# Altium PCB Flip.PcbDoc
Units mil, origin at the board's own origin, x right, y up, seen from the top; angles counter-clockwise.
Board outline 2000 x 1094.88 mil, 4 copper layers (Top Layer, Signal 1, Signal 2, Bottom Layer), stack 23.756 mil thick; 95 components, 90 nets, 410 pads, 177 vias.
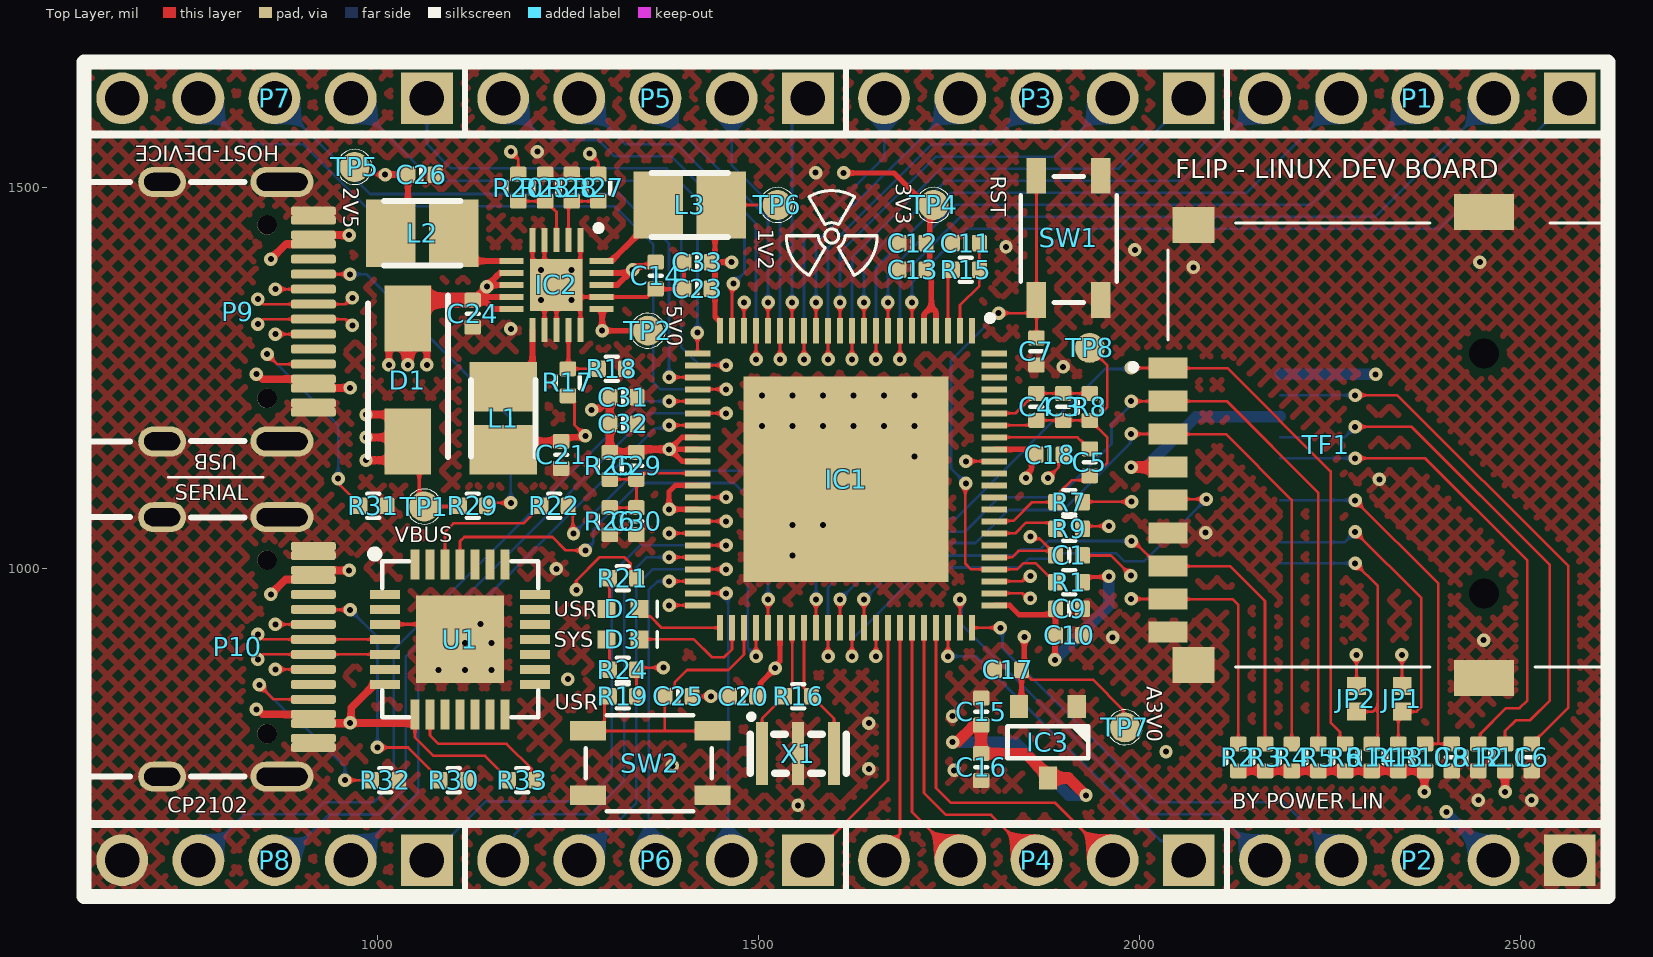
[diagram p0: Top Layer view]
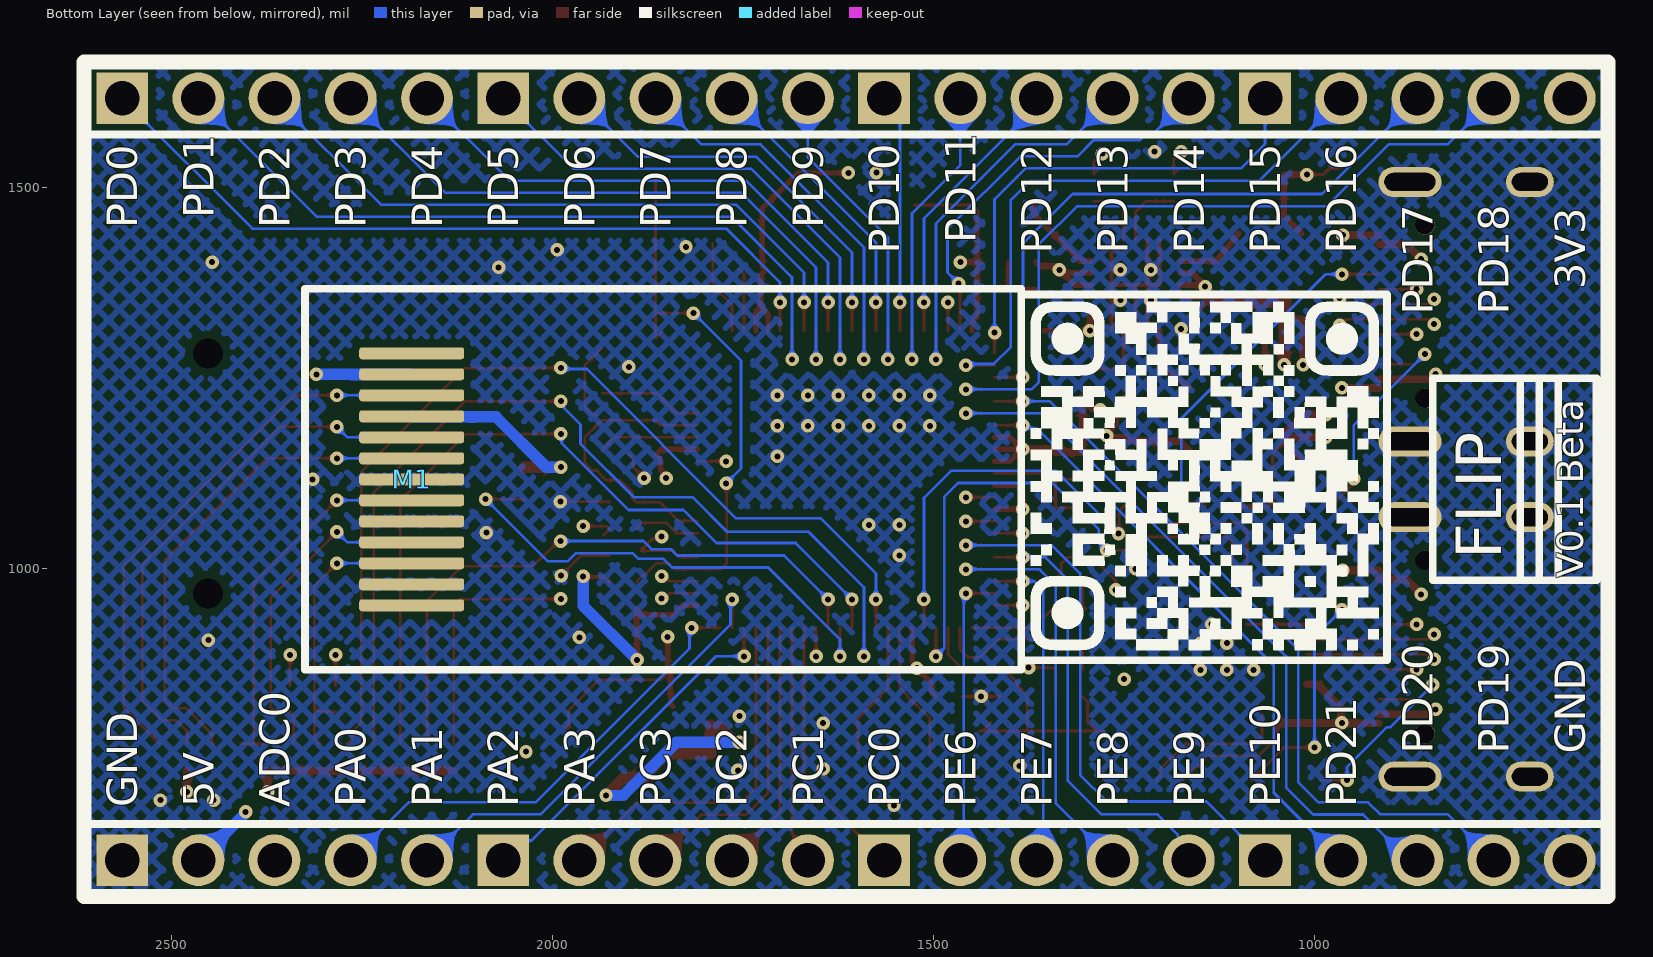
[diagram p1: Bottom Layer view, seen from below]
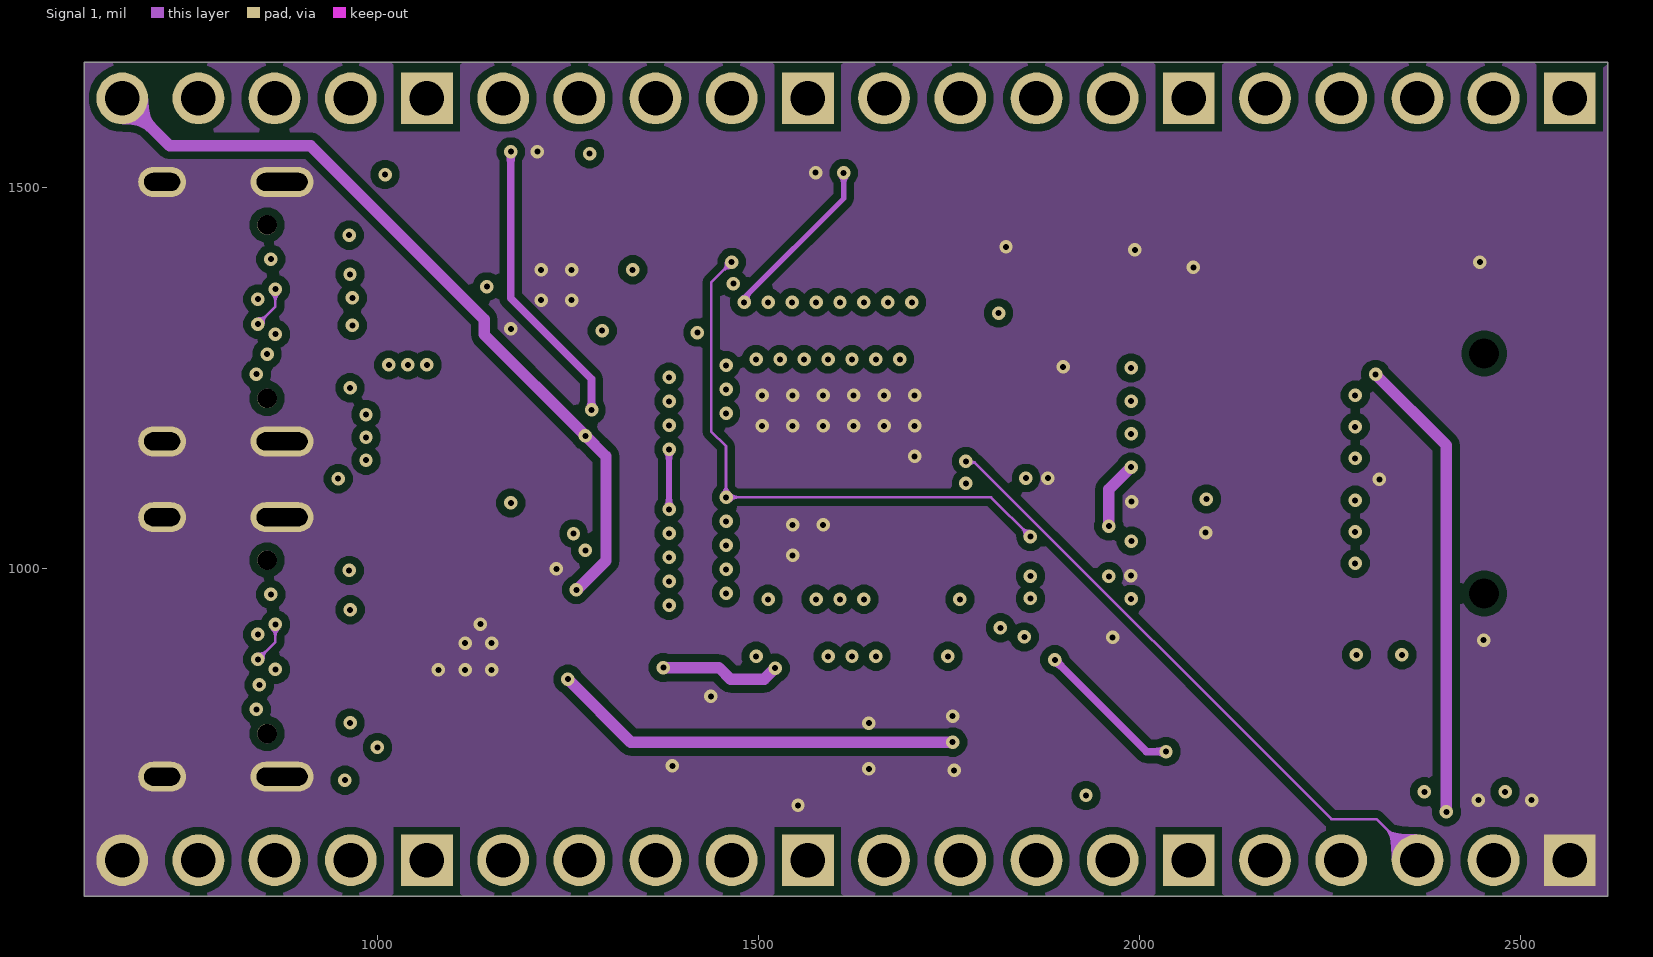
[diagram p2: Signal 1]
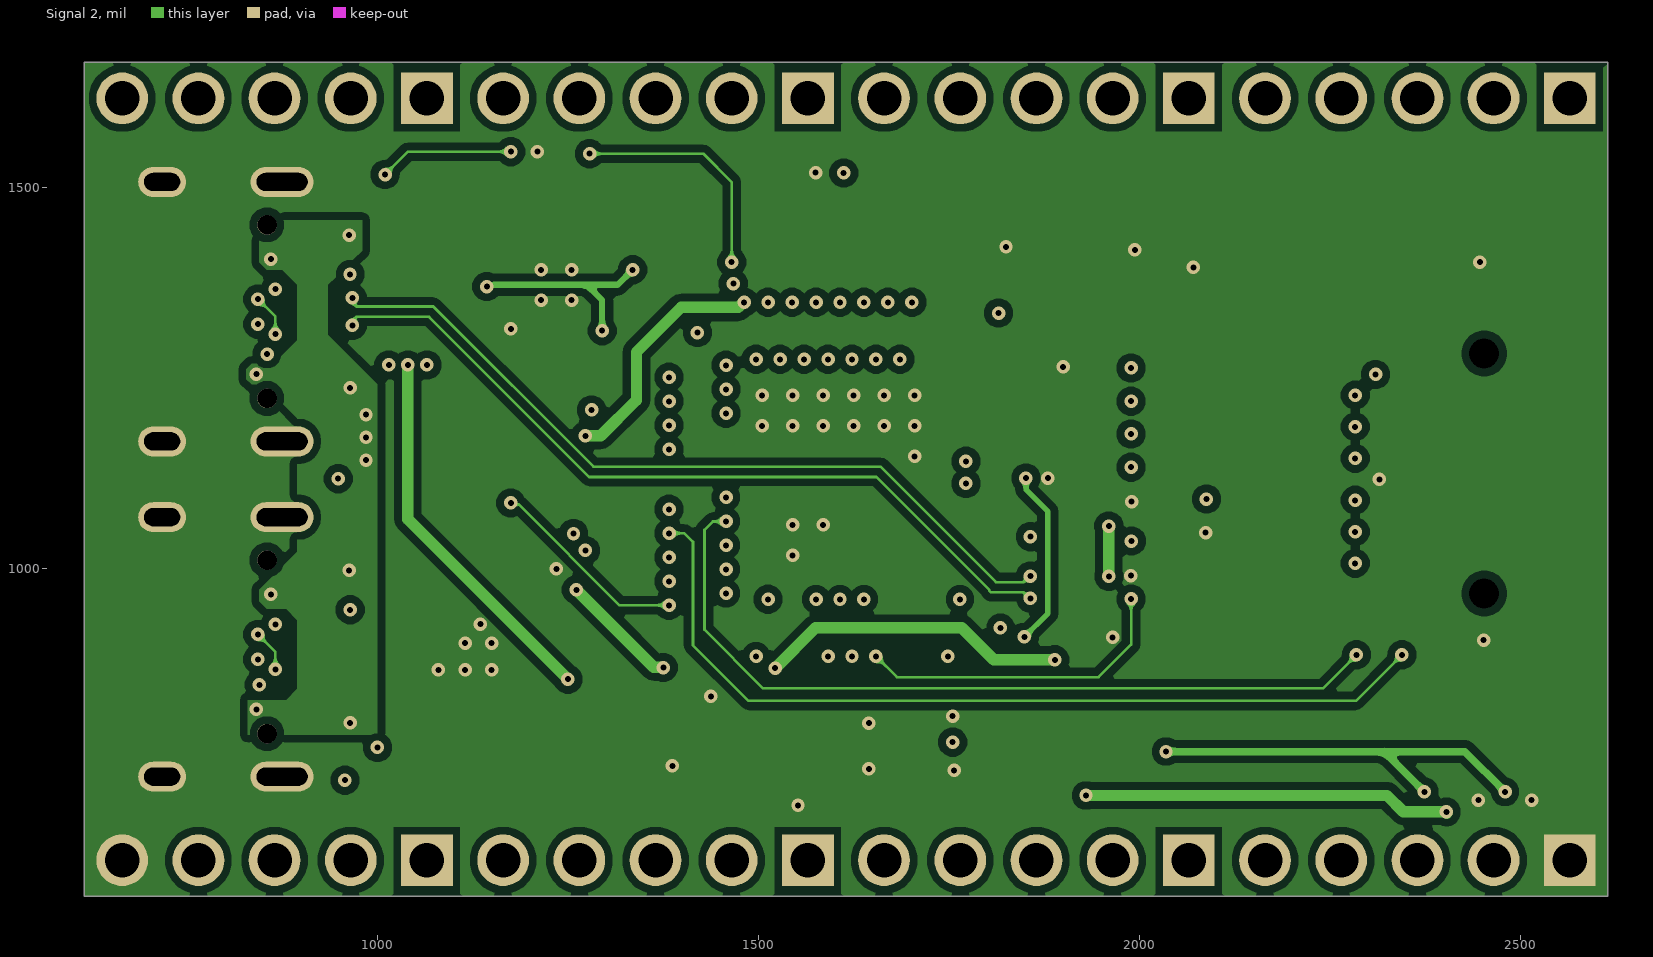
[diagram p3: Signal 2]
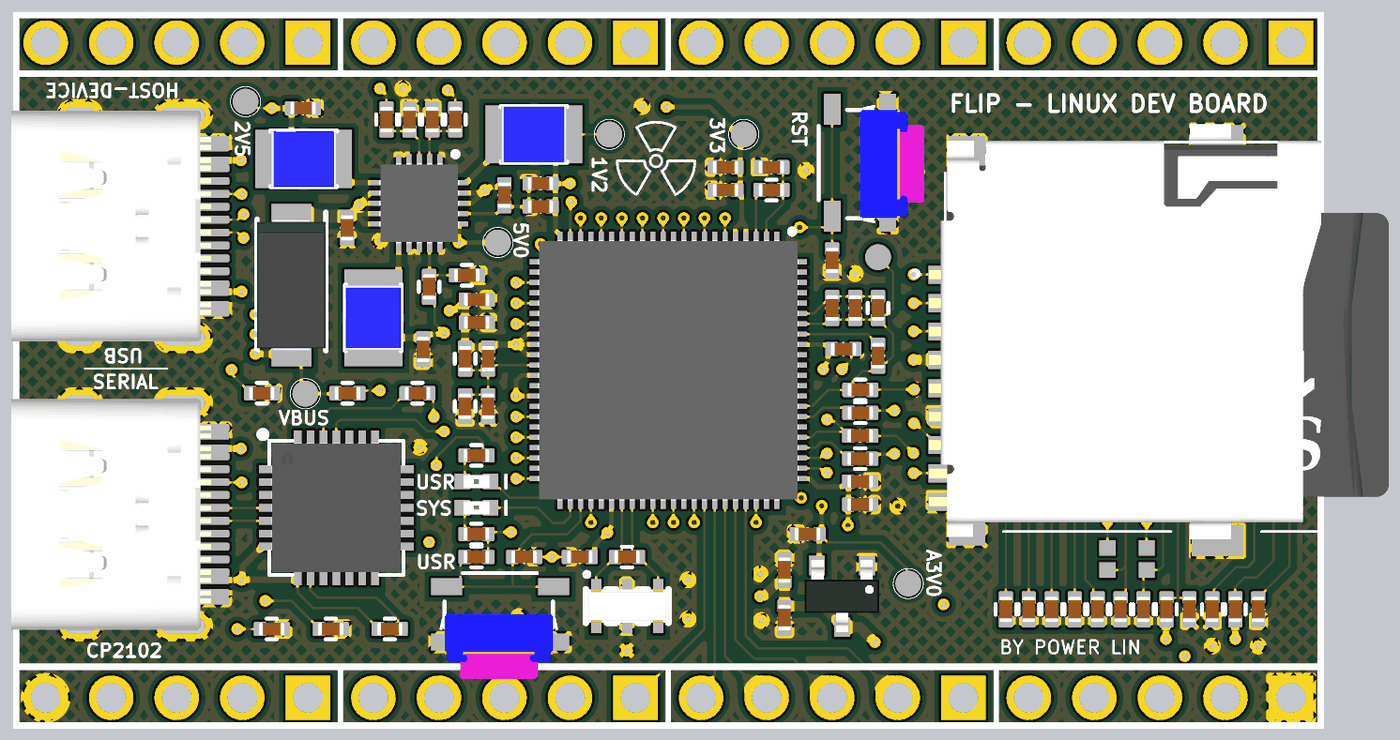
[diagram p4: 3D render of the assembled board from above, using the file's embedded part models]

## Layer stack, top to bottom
Top Solder: solder mask 0.4, Solder Resist, Dk 3.5
Top Layer: signal copper 1.4
Dielectric 2: prepreg 2.8, PP-006, Dk 4.1
Signal 1: signal copper 1.378
Dielectric 1: dielectric 12.6, FR-4, Dk 4.8
Signal 2: signal copper 1.378
Dielectric 3: prepreg 2.8, PP-006, Dk 4.1
Bottom Layer: signal copper 1.4
Bottom Solder: solder mask 0.4, Solder Resist, Dk 3.5

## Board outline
615,570 615,1664.88 2615,1664.88 2615,570

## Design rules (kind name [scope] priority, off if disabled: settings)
Clearance [All] p1: gap=0 ignorepadtopadclearanceinfootprint=TRUE except(10: Arc-Fill Arc-Poly Arc-Region Track-Fill Track-Poly Track-Region SMDPad-Fill SMDPad-Poly SMDPad-Region THPad-Fill THPad-Poly THPad-Region Via-Fill Via-Poly Via-Region Fill-Fill Fill-Poly Fill-Region Poly-Poly Poly-Region Region-Region)
DiffPairsRouting [All] p1: maxlimit=10 minlimit=10 mostfreqgap=10 toplayer_minwidth=3.5 toplayer_maxwidth=15 toplayer_prefwidth=3.5 midlayer1_minwidth=3.5 midlayer1_maxwidth=15 midlayer1_prefwidth=3.5 midlayer2_minwidth=3.5 midlayer2_maxwidth=15 midlayer2_prefwidth=3.5 bottomlayer_minwidth=3.5 bottomlayer_maxwidth=15 bottomlayer_prefwidth=3.5 maxuncoupledlength=500
PolygonConnect [All] p1: connectstyle=Direct reliefconductorwidth=10 reliefentries=4 polygonreliefangle="90 Angle" airgapwidth=10
RoutingVias [All] p1: holewidth=7.87 width=17.72 viastyle="Through Hole" minholewidth=7.87 minwidth=17.72 maxholewidth=7.87 maxwidth=17.72
SolderMaskExpansion [All] p1: expansion=4 istentingtop=FALSE
Width [All] p1: maxlimit=100 minlimit=3.5 preferedwidth=3.5
29 further rules are at their usual default settings.

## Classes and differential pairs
differential pair USB: +USB_P -USB_N
differential pair USB_CP: +USB_CP_P -USB_CP_N

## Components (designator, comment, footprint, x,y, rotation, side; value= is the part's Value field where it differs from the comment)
C1 "100nF" CAP-0402 1907.72,1017.44 r180 top
C3 "100nF" CAP-0402 1900,1212.44 r90 top
C4 "10uF" CAP-0402 1865,1212.44 r270 top
C5 "1uF" CAP-0402 1935,1139.72 r90 top
C6 "10uF" CAP-0402 2515,752.44 r270 top
C7 "100nF" CAP-0402 1865,1285.16 r90 top
C8 "10uF" CAP-0402 2410,752.44 r270 top
C9 "100nF" CAP-0402 1907.72,947.44 r0 top
C10 "10uF" CAP-0402 1907.72,912.44 r180 top
C11 "1uF" CAP-0402 1772.28,1427.44 r0 top
C12 "10uF" CAP-0402 1702.28,1427.44 r0 top
C13 "100nF" CAP-0402 1702.28,1392.44 r0 top
C14 "100nF" CAP-0402 1365,1384.72 r90 top
C15 "10uF" CAP-0402 1792.28,812.44 r270 top
C16 "1uF" CAP-0402 1792.28,739.72 r270 top
C17 "10uF" CAP-0402 1827.6,867.44 r0 top
C18 "1uF" CAP-0402 1882.21,1149.82 r0 top
C20 "10uF" CAP-0402 1480,832.44 r0 top
C21 "10uF" CAP-0402 1241,1149.44 r90 top
C23 "100nF" CAP-0402 1420,1367.44 r0 top
C24 "10uF" CAP-0402 1125,1334.72 r90 top
C25 "100nF" CAP-0402 1395,832.44 r180 top
C26 "10uF" CAP-0402 1057.72,1517.44 r180 top
C29 "100nF" CAP-0402 1340,1135.16 r270 top
C30 "100nF" CAP-0402 1340,1062.44 r270 top
C31 "10uF" CAP-0402 1322.72,1225.16 r180 top
C32 "100nF" CAP-0402 1322.72,1190.16 r180 top
C33 "10uF" CAP-0402 1420,1402.44 r0 top
D1 "SS34" DO-214AC/SMA 1040,1247.44 r270 top
D2 "RED" LED-0402 1322.28,947.44 r0 top
D3 "RED" LED-0402 1322.28,907.44 r0 top
IC1 "F1C200S" QFN88P_10X10mm 1615,1117.44 r270 top locked
IC2 "EA3036C" QFN3mmx3mm-20 1235,1372.44 r270 top
IC3 "XC6206P302MR-G" SOT-23-3 1880,772.44 r90 top
JP1 "Select" 选择焊点-0402 2345,829.44 r270 top
JP2 "Select" 选择焊点-0402 2285,829.44 r270 top
L1 "2.2uH" L-1008 1165,1197.44 r270 top
L2 "2.2uH" L-1008 1058.66,1440.16 r180 top
L3 "2.2uH" L-1008 1410,1477.44 r0 top
M1 "OLED_12880" OLED_0.78INCH_12880 2185,1117.44 r0 bottom locked
P1 "HDR1x5" HDR1X5_2.54_180_BLANK 2565,1617.44 r180 top
P2 "HDR1x5" HDR1X5_2.54_180_BLANK 2565,617.44 r180 top
P3 "HDR1x5" HDR1X5_2.54_180_BLANK 2065,1617.44 r180 top
P4 "HDR1x5" HDR1X5_2.54_180_BLANK 2065,617.44 r180 top
P5 "HDR1x5" HDR1X5_2.54_180_BLANK 1565,1617.44 r180 top
P6 "HDR1x5" HDR1X5_2.54_180_BLANK 1565,617.44 r180 top
P7 "HDR1x5" HDR1X5_2.54_180_BLANK 1065,1617.44 r180 top
P8 "HDR1x5" HDR1X5_2.54_180_BLANK 1065,617.44 r180 top
P9 "TYPE-C-31-M-12" Type-C_16+4P 816.64,1337.44 r180 top locked
P10 "TYPE-C-31-M-12" Type-C_16+4P 816.64,897.44 r180 top locked
R1 "10k" R-0402 1907.72,982.44 r0 top
R2 "10k" R-0402 2130,752.44 r270 top
R3 "10k" R-0402 2165,752.44 r270 top
R4 "10k" R-0402 2200,752.44 r270 top
R5 "10k" R-0402 2235,752.44 r270 top
R6 "10k" R-0402 2270,752.44 r270 top
R7 "0R" R-0402 1908,1087.44 r0 top
R8 "10k" R-0402 1935,1212.44 r270 top
R9 "0R" R-0402 1908,1052.44 r0 top
R10 "10k" R-0402 2375,752.44 r90 top
R11 "5.1k" R-0402 2480,752.44 r90 top
R12 "560k" R-0402 2445,752.44 r90 top
R13 "10k" R-0402 2340,752.44 r90 top
R14 "10k" R-0402 2305,752.44 r90 top
R15 "22R" R-0402 1772.28,1392.44 r0 top
R16 "1M" R-0402 1552.01,832.44 r0 top
R17 "510k" R-0402 1250,1244.72 r270 top
R18 "110k" R-0402 1307.72,1262.44 r180 top
R19 "10k" R-0402 1322.28,832.44 r0 top
R20 "316k" R-0402 1185,1500.16 r90 top
R21 "5.1k" R-0402 1322.28,987.44 r180 top
R22 "200R" R-0402 1232.28,1082.44 r180 top
R23 "100k" R-0402 1220,1500.16 r270 top
R24 "5.1k" R-0402 1322.28,867.44 r180 top
R25 "5.1k" R-0402 1305,1135.16 r270 top
R26 "5.1k" R-0402 1305,1062.44 r270 top
R27 "100k" R-0402 1290,1500.16 r90 top
R28 "100k" R-0402 1255,1500.16 r270 top
R29 "56k" R-0402 1125.43,1082.44 r0 top
R30 "5.1k" R-0402 1100,722.44 r0 top
R31 "5.1k" R-0402 994.82,1082.44 r0 top
R32 "5.1k" R-0402 1010,722.44 r0 top
R33 "10k" R-0402 1190,722.44 r180 top
SW1 "KEY" KEY-4P-4.2*3.4*2.5 1907.32,1434.13 r90 top
SW2 "KEY" KEY-4P-4.2*3.4*2.5 1358.31,744.76 r0 top
TF1 "TF-01A" TF_1 2245,1162.44 r0 top locked
TP1 "TestPoint" TestPoint 1061.26,1081.58 r0 top
TP2 "TestPoint" TestPoint 1355,1312.44 r0 top
TP4 "TestPoint" TestPoint 1730,1477.44 r0 top
TP5 "TestPoint" TestPoint 970,1527.44 r0 top
TP6 "TestPoint" TestPoint 1525,1477.44 r0 top
TP7 "TestPoint" TestPoint 1981.06,791.87 r0 top
TP8 "TestPoint" TestPoint 1935,1290 r0 top
U1 "CP2102" QFN28 1108.42,907.44 r0 top locked
X1 "24MHz" SMD3213-3P 1552.11,757.44 r0 top

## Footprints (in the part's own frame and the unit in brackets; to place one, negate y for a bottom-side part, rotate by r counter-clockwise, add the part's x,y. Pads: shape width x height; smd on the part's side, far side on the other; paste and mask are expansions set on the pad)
CAP-0402 [mm]
  rrect25% 0.5x0.55 smd: 1(-0.45,0) 2(0.45,0)
  silkscreen extent 0,-0.2 0,0.2, body extent -0.5,-0.25 0.5,0.25, height 0.6
DO-214AC/SMA [mm]
  rect 2.2x1.55 smd: 1(2.05,0) 2(-2.05,0)
  silkscreen extent -2.83,-1.33 2.55,1.33, body extent -2.55,-1.33 2.55,1.33, height 2.29
HDR1X5_2.54_180_BLANK [mm]
  rect 1.725x1.725 hole 1.15: 1(0,0)
  round 1.725 hole 1.15: 2(2.54,0) 3(5.08,0) 4(7.62,0) 5(10.16,0)
  silkscreen extent -1.27,-1.2 11.43,1.2
KEY-4P-4.2*3.4*2.5 [mm] "SKRPABE010"
  rect 1.2x0.65 smd: 1(-2.075,1.075) 1(2.075,1.075) 2(-2.075,-1.075) 2(2.075,-1.075)
  silkscreen extent -2.15,-1.6 2.05,1.6, body extent -2.35,-1.6 2.25,1.6, height 2.5
L-1008 [mm]
  rect 1.65x2.25 smd: 1(-1.05,0) 2(1.05,0)
  silkscreen extent -1.28,-1.07 1.28,1.07, body extent -1.28,-1.07 1.28,1.07, height 1.2
LED-0402 [mm]
  rect 0.6x0.6 smd: 1(-0.55,0) 2(0.55,0)
  silkscreen extent 1.14,-0.25 1.14,0.25, body extent -0.5,-0.25 0.5,0.25, height 0.5
OLED_0.78INCH_12880 [mm]
  rrect50% 3.5x0.4 smd: 1(0,-4.2) 2(0,-3.5) 3(0,-2.8) 4(0,-2.1) 5(0,-1.4) 6(0,-0.7) 7(0,0) 8(0,0.7) 9(0,1.4) 10(0,2.1) 11(0,2.8) 12(0,3.5) 13(0,4.2)
  silkscreen extent -20.32,-6.35 3.56,6.35, body extent -20.18,-6.25 7.54,6.25, height 1.55
QFN3mmx3mm-20 [mm]
  rect 0.8x0.2 smd: 1(-1.5,0.8) 2(-1.5,0.4) 3(-1.5,0) 4(-1.5,-0.4) 5(-1.5,-0.8) 11(1.5,-0.8) 12(1.5,-0.4) 13(1.5,0) 14(1.5,0.4) 15(1.5,0.8)
  rect 0.2x0.8 smd: 6(-0.8,-1.5) 7(-0.4,-1.5) 8(0,-1.5) 9(0.4,-1.5) 10(0.8,-1.5) 16(0.8,1.5) 17(0.4,1.5) 18(0,1.5) 19(-0.4,1.5) 20(-0.8,1.5)
  rect 1.75x1.75 smd: 21(0,0)
  silkscreen extent -2,1.3 -1.8,1.5, body extent -1.55,-1.55 1.55,1.55, height 0.8
QFN28 [mm]
  rect 1x0.3 smd: 1(-2.5,1.5) 2(-2.5,1) 3(-2.5,0.5) 4(-2.5,0) 5(-2.5,-0.5) 6(-2.5,-1) 7(-2.5,-1.5) 15(2.5,-1.5) 16(2.5,-1) 17(2.5,-0.5) 18(2.5,0) 19(2.5,0.5) 20(2.5,1) 21(2.5,1.5)
  rect 0.3x1 smd: 8(-1.5,-2.5) 9(-1,-2.5) 10(-0.5,-2.5) 11(0,-2.5) 12(0.5,-2.5) 13(1,-2.5) 14(1.5,-2.5) 22(1.5,2.5) 23(1,2.5) 24(0.5,2.5) 25(0,2.5) 26(-0.5,2.5) 27(-1,2.5) 28(-1.5,2.5)
  rect 2.921x2.921 smd paste-3.2: 29(0,0)
  silkscreen extent -2.97,-2.6 2.6,2.97, body extent -2.5,-2.5 2.5,2.5, height 1
QFN88P_10X10mm [mm]
  rect 0.85x0.2 smd: 1(-4.95,4.2) 2(-4.95,3.8) 3(-4.95,3.4) 4(-4.95,3) 5(-4.95,2.6) 6(-4.95,2.2) 7(-4.95,1.8) 8(-4.95,1.4) 9(-4.95,1) 10(-4.95,0.6) 11(-4.95,0.2) 12(-4.95,-0.2) 13(-4.95,-0.6) 14(-4.95,-1) 15(-4.95,-1.4) 16(-4.95,-1.8) 17(-4.95,-2.2) 18(-4.95,-2.6) 19(-4.95,-3) 20(-4.95,-3.4) 21(-4.95,-3.8) 22(-4.95,-4.2) 45(4.95,-4.2) 46(4.95,-3.8) 47(4.95,-3.4) 48(4.95,-3) 49(4.95,-2.6) 50(4.95,-2.2) 51(4.95,-1.8) 52(4.95,-1.4) 53(4.95,-1) 54(4.95,-0.6) 55(4.95,-0.2) 56(4.95,0.2) 57(4.95,0.6) 58(4.95,1) 59(4.95,1.4) 60(4.95,1.8) 61(4.95,2.2) 62(4.95,2.6) 63(4.95,3) 64(4.95,3.4) 65(4.95,3.8) 66(4.95,4.2)
  rect 0.2x0.85 smd: 23(-4.2,-4.95) 24(-3.8,-4.95) 25(-3.4,-4.95) 26(-3,-4.95) 27(-2.6,-4.95) 28(-2.2,-4.95) 29(-1.8,-4.95) 30(-1.4,-4.95) 31(-1,-4.95) 32(-0.6,-4.95) 33(-0.2,-4.95) 34(0.2,-4.95) 35(0.6,-4.95) 36(1,-4.95) 37(1.4,-4.95) 38(1.8,-4.95) 39(2.2,-4.95) 40(2.6,-4.95) 41(3,-4.95) 42(3.4,-4.95) 43(3.8,-4.95) 44(4.2,-4.95) 67(4.2,4.95) 68(3.8,4.95) 69(3.4,4.95) 70(3,4.95) 71(2.6,4.95) 72(2.2,4.95) 73(1.8,4.95) 74(1.4,4.95) 75(1,4.95) 76(0.6,4.95) 77(0.2,4.95) 78(-0.2,4.95) 79(-0.6,4.95) 80(-1,4.95) 81(-1.4,4.95) 82(-1.8,4.95) 83(-2.2,4.95) 84(-2.6,4.95) 85(-3,4.95) 86(-3.4,4.95) 87(-3.8,4.95) 88(-4.2,4.95)
  rect 6.84x6.84 smd: 89(0,0)
  silkscreen extent -5.47,4.7 -5.28,4.9, body extent -5.05,-5.05 5.05,5.05, height 0.9
R-0402 [mm]
  rrect25% 0.5x0.55 smd: 1(-0.45,0) 2(0.45,0)
  silkscreen extent -0.2,-0.4 0.2,0.4, body extent -0.5,-0.25 0.5,0.25, height 0.6
SMD3213-3P [mm]
  rect 0.4x2.1 smd: 1(-1.2,0) 2(0,0) 3(1.2,0)
  silkscreen extent -1.6,-0.65 1.6,1.27, body extent -1.6,-0.65 1.6,0.65, height 0.7
SOT-23-3 [mil]
  rect 30x24 smd: 1(47,-38) 2(47,38) 3(-47,0)
  silkscreen extent -21,-53 21,53, body extent -55,-57 55,57, height 51
TestPoint [mm]
  round 1 smd: 1(0,0)
TF_1 [mm]
  rect 1.3x0.7 smd: 1(-5.275,2.56) 2(-5.275,1.46) 3(-5.275,0.36) 4(-5.275,-0.74) 5(-5.275,-1.84) 6(-5.275,-2.94) 7(-5.275,-4.04) 8(-5.275,-5.14) 9(-5.275,-6.24)
  rect 1.4x1.2 smd: 10(-4.425,-7.34) 13(-4.425,7.34)
  rect 2x1.2 smd: 11(5.275,-7.76) 12(5.275,7.76)
  round 0.5 hole 1 unplated: 14(5.275,-4.95) 15(5.275,3.05)
  silkscreen extent -6.53,-7.4 9.23,7.4, body extent -5.9,-7.7 11.92,8.4, height 2.05
Type-C_16+4P [mm]
  round 0.65 hole 0.65: 0(-0.98,2.89) 0(-0.98,-2.89)
  oval 1.6x1 hole 0.6 slot 1.2 at 0 deg: 1(2.52,4.325) 2(2.52,-4.325)
  oval 2.1x1 hole 0.6 slot 1.7 at 0 deg: 3(-1.48,-4.325) 4(-1.48,4.325)
  rrect50% 1.5x0.3 smd: A1(-2.52,-3.35) A4(-2.52,-2.55) A5(-2.52,-1.25) A6(-2.52,-0.25) A7(-2.52,0.25) A8(-2.52,1.25) A9(-2.52,2.55) A12(-2.52,3.35) B1(-2.52,3.05) B4(-2.52,2.25) B5(-2.52,1.75) B6(-2.52,0.75) B7(-2.52,-0.75) B8(-2.52,-1.75) B9(-2.52,-2.25) B12(-2.52,-3.05)
  silkscreen extent -0.22,-4.33 5.12,4.33, body extent -2.57,-4.48 5.18,4.48, height 3.26
选择焊点-0402 [mm]
  rect 0.6x0.62 smd: 1(-0.432,0) 2(0.432,0)

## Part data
C1 C3 C4 C5 C6 C7 C8 C9 C10 C11 C12 C13 C14 C15 C16 C17 C18 C20 C21 C23 C24 C25 C26 C29 C30 C31 C32 C33: library part CAP, "贴片电容", Package=0402, SuppliersPartNumber=C52923
D1: library part DIODE, "肖特基二极管", Package=SMA(DO-214AC), SuppliersPartNumber=C22452
D2 D3: library part LED, "发光二极管", Package=0603, SuppliersPartNumber=C2290
IC1: library part F1C100S/F1C200S, "SOC", Manufacturer_Name="Allwinner Technology"
IC2: "EA3036 is a 3CH power management IC for applications powered by one Li-Ion battery or a DC 5V adapter."
IC3: library part XC6206, "LDO", Manufacturer_Name=Torex, Manufacturer_Part_Number=XC6206P122MR-G, Mouser Part Number=865-XC6206P122MR-G
JP1 JP2: "选择焊点"
L1 L2 L3: library part INDUCTOR, "SRN2512-2R2M", Package=0402, SuppliersPartNumber=C32041
M1: "OLED屏"
P1 P2 P3 P4 P5 P6 P7 P8: library part HDR1x5_2.54, "Header", Manufacturer_Name="FCI Electronics", Manufacturer_Part_Number=10129378-905001BLF, Mouser Part Number=649-1012937890501BLF
P9 P10: library part USB_Type-C_16+4P, "USB Type-C 座子"
R1 R2 R3 R4 R5 R6 R7 R8 R9 R10 R11 R12 R13 R14 R15 R16 R19 R21 R22 R24 R25 R26 R29 R30 R31 R32 R33: library part RES, "贴片电阻", Package=0805, SuppliersPartNumber=C17798
R17 R18: library part RES, "RC0402FR-07510KL", Package=0805, SuppliersPartNumber=C17798
R20: library part RES, "RC0402FR-07316KL", Package=0805, SuppliersPartNumber=C17798
R23 R27 R28: library part RES, "RC0402FR-07100KL", Package=0805, SuppliersPartNumber=C17798
SW1 SW2: "按键开关"
TF1: library part TF卡座_8脚自弹, "与TF-01A封装相似则可替换"
TP1 TP2 TP4 TP5 TP6 TP7 TP8: "测试点"
U1: "CP2102-GMR"
X1: library part XTAL, "村田无源晶振"

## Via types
v1: diameter 17.72, hole 7.87, Top Layer to Bottom Layer, 177 vias

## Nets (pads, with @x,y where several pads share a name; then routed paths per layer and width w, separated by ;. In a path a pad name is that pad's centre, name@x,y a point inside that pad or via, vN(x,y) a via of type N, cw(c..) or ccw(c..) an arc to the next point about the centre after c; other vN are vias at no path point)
ADC0: IC1.79 P2.3 | length 846.8
  Top Layer w3.5: v1(1772.48,1141.06) IC1.79
  Signal 1 w3.5: v1(1772.48,1141.06) 1774.01,1139.54 1783.91,1139.54 2252,671.44 2311,671.44 P2.3
AGND: C3.1 C4.2 C5.1 IC1.74 IC1.82 R7.1 R8.2 TP8.1 | length 485.6
  Top Layer w3.5: IC1.74 1810.42,1062.86 1834.86,1062.86 1859.44,1087.44 R7.1 1896.19,1093.35 1896.19,1101.19 1911.08,1116.08 1929.07,1116.08 C5.1 1942,1129 1947.66,1129 1958.08,1139.43 1958.08,1172.37 1935.73,1194.72 R8.2 C3.1 C4.2 1858.64,1188.37 1809.94,1188.37 IC1.82 ; TP8.1 1958.08,1266.92 1958.08,1212.14 1947.66,1201.72 R8.2@1942,1201.72
AVCC_3V0: C17.2 C18.1 IC1.80 IC3.2 TP7.1 | length 599.3
  Top Layer w3.5: C17.2@1845.31,866.84 C17.2@1853.35,858.8 ; C17.2@1853.95,858.8 1858.31,854.44 1939,854.44 1978.68,814.76 TP7.1@1978.68,794.24
  Top Layer w7: IC1.80 1809.94,1156.75 1857.56,1156.75 C18.1 1858.43,1143.75 1858.43,1130.16 1851.18,1122.91 v1(1851.18,1119.06) ; IC3.2 1845.31,822.76 1845.31,866.84 C17.2 1849,871.13 v1(1849,910.44) ; TP7.1@1978.68,794.24 TP7.1
  Signal 2 w7: v1(1849,910.44) 1880,941.44 1880,1075 1851.17,1103.83 v1(1851.18,1119.06)
GND: C1.1 C6.2 C7.1 C8.2 C9.2 C10.1 C11.1 C12.1 C13.1 C14.1 C15.1 C16.2 C17.1 C18.2 C20.1 C21.1 C23.1 C24.1 C25.1 C26.1 C30.2 C31.1 C32.1 C33.1 IC1.89 IC2.1 IC2.4 IC2.5 IC2.12 IC2.13 IC2.15 IC2.17 IC2.21 IC3.1 M1.7 M1.9 M1.12 P2.1 P8.5 P9.1 P9.2 P9.3 P9.4 P9.A1 P9.A12 P9.B1 P9.B12 P10.1 P10.2 P10.3 P10.4 P10.A1 P10.A12 P10.B1 P10.B12 R7.2 R12.1 R18.1 R23.1 R26.2 R28.1 R30.2 R31.2 R32.2 SW1.2 SW2.2 TF1.6 TF1.9 TF1.10 TF1.11 TF1.12 TF1.13 U1.3 U1.29 X1.2 | length 936
  Top Layer w3.5: C14.1 1401.85,1367.01 C23.1 ; C25.1 C20.1 ; v1(1880,1119) 1894.29,1133.29 1894.29,1144.19 C18.2 ; C1.1 1962.56,1017.44 v1(1989,991) ; R7.2 1926.28,1088 v1(1990,1088)
  Top Layer w5: U1.3 U1.29@1088.74,927.13 ; IC2.5 1203.5,1372.44 IC2.21@1219.25,1372.44 ; IC2.12 IC2.21@1219.25,1372.44 ; IC2.4 IC2.21@1219.25,1372.44 ; IC2.13 IC2.21 ; IC2.15 IC2.21@1266.5,1357.15 ; IC2.1 IC2.21@1266.5,1372.44 ; C23.1@1401.85,1367.01 C14.1 1364.02,1367.01 1353.7,1356.69 IC2.17 1266.95,1356.69 IC2.21@1266.5,1357.15 ; C23.1 C33.1 ; IC2.21@1219.25,1372.44 IC2.21 ; IC2.21 IC2.21@1266.5,1372.44 ; IC2.21@1266.5,1357.15 IC2.21@1266.5,1372.44
  other v1: 1552,689.44 2445,696.44 2515,696.44 1757,735.44 1645,737.44 1387,741.44 1645,797.44 1755,806.44 1437.5,832.44 1080,867.44 1115,867.44 1150,867.44 1115,902.44 1150,902.44 2452,906.44 1965,910 1135,927.44 1235,1000 1545,1017.44 2087,1047.44 1545,1057.44 1585,1057.44 2315,1117.44 1705,1147.44 1505,1187.44 1545,1187.44 1585,1187.44 1625,1187.44 1665,1187.44 1705,1187.44 1505,1227.44 1545,1227.44 1585,1227.44 1625,1227.44 1665,1227.44 1705,1227.44 1900,1265 1175,1315 1215,1352.44 1255,1352.44 1215,1392.44 1255,1392.44 2071,1395.44 2447,1402.44 1994,1418.44 1825,1422.44 1575,1520 1210,1547.44
KEY_USR: C25.2 IC1.47 R19.1 SW2.1 | length 442
  Top Layer w3.5: SW2.1@1276.61,787.09 SW2.1@1286.91,787.09 ; R19.1 1297.96,825.83 1297.96,798.13 SW2.1@1286.91,787.09 ; SW2.1@1425,798.13 SW2.1@1436.05,787.09 ; SW2.1@1440,787.09 SW2.1@1436.05,787.09 ; IC1.47 1481.14,887.51 1460.67,867.03 1406.59,867.03 1390.12,850.56 1390.12,846.65 1377.28,833.81 C25.2 1377.28,787.37 1377,787.09 ; SW2.1@1286.91,787.09 1377,787.09 ; 1377,787.09 SW2.1@1436.05,787.09
LED_SYS: D3.2 IC1.46 | length 163.9
  Top Layer w3.5: D3.2 1415.27,907.44 1438.79,883.92 1455.2,883.92 1465.39,894.12 IC1.46
LED_USR: D2.2 IC1.45 | length 116
  Top Layer w3.5: D2.2 1354,937.38 1358.27,937.38 1373.09,922.56 IC1.45
NetC3_2: C3.2 C4.1 IC1.83 R8.1 | length 135.7
  Top Layer w3.5: IC1.83@1809.92,1204.1 1837.25,1204.1 C4.1@1863.66,1230.51 ; C4.1@1864.02,1230.16 C4.1 C3.2 R8.1
NetC5_2: C5.2 IC1.81 | length 131.4
  Top Layer w3.5: IC1.81 1918.9,1172.56 1934.02,1157.44 C5.2
NetC6_1: C6.1 M1.3 | length 724.4
  Top Layer w3.5: v1(2283.34,1227.68) 2338.7,1227.68 2563.01,1003.37 2563.01,818.16 2523.64,778.8 2523.64,778.2 2515.6,770.16 C6.1
  Bottom Layer w3.5: M1.3 v1(2283.34,1227.68)
NetC7_2: C7.2 IC1.70 R1.1 SW1.1 | length 772.8
  Top Layer w3.5: v1@1771.53,1111.97 1771.53,1006.84 1779.03,999.33 IC1.70 1839.69,999.33 1847.8,1007.44 1863.64,1007.44 1880,991.08 1881.96,991.08 1890,983.04 R1.1@1890,982.68 ; v1(1815.28,1335.56) SW1.1@1865,1335.56 ; C7.2@1856.36,1310.91 1864.4,1302.87 C7.2 SW1.1@1865,1335.56 ; SW1.1@1865,1515.83 1865,1352.44 SW1.1@1865,1335.56
  Bottom Layer w3.5: v1(1772.48,1111.97) 1752.82,1131.63 1752.82,1273.1 v1(1815.28,1335.56)
NetC8_1: C8.1 M1.8 R10.2 | length 498.3
  Top Layer w3.5: v1(2283.34,1089.88) 2392.51,980.71 2392.51,770.16 ; R10.2 2390.21,770.16 2392.51,770.16 ; C8.1 2392.51,770.16
  Bottom Layer w3.5: M1.8 v1(2283.34,1089.88)
NetC11_2: C11.2 IC1.2 R15.2 | length 125.6
  Top Layer w3.5: IC1.2@1764.63,1312.34 1764.63,1345.88 1790,1371.26 C11.2
NetC29_2: C29.2 C30.1 IC1.33 R25.2 R26.1 | length 190.7
  Top Layer w3.5: R26.1 C30.1 C29.2 ; R25.2 C29.2 ; IC1.33 1349.24,1125.31 1341.37,1117.44 C29.2
NetD2_A: D2.1 R21.2 | length 41.6
  Top Layer w3.5: D2.1 1304.57,951.38 R21.2
NetD3_A: D3.1 R24.2 | length 41.6
  Top Layer w3.5: D3.1 1304.57,903.5 R24.2
NetIC1_3: IC1.3 R15.1 | length 82.5
  Top Layer w3.5: IC1.3 1748.9,1312.36 1748.9,1386.77 R15.1
NetIC1_51: IC1.51 R16.1 X1.1 | length 182.2
  Top Layer w3.5: X1.1 1504.87,803.4 1525.27,823.8 1526.46,823.8 1534.49,831.84 1534.49,832.44 1534.49,833.73 1544.34,843.57 IC1.51@1544.34,922.56
NetIC1_52: IC1.52 R16.2 X1.3 | length 182.8
  Top Layer w3.5: IC1.52 1559.88,843.57 1569.72,833.73 R16.2@1569.72,831.84 ; R16.2 R16.2@1569.72,831.84 ; X1.3 1599.35,803.4 1578.95,823.8 1577.76,823.8 R16.2@1569.72,831.84
NetIC1_73: IC1.73 R9.1 | length 89.5
  Top Layer w3.5: IC1.73 1837.13,1046.57 1851,1060.44 1882.28,1060.44 R9.1
NetIC2_2: IC2.2 R27.1 R28.2 | length 87.3
  Top Layer w3.5: IC2.2 1250.75,1476.6 R28.2 R27.1
NetIC2_3: IC2.3 R20.1 R23.2 | length 92.7
  Top Layer w3.5: R20.1 1220.98,1482.44 1235,1468.43 IC2.3
NetIC2_6: IC2.6 L2.1 | length 93.5
  Top Layer w8: L2.1 1128.48,1403.94 IC2.6
NetIC2_11: IC2.11 L1.1 | length 94
  Top Layer w8: L1.1 1203.5,1267.26 IC2.11
NetIC2_14: IC2.14 R17.1 R18.2 | length 91
  Top Layer w3.5: R17.1 R18.2
  Top Layer w5: R17.1@1250.75,1268.28 IC2.14
  Top Layer w8: R17.1 R17.1@1250.75,1268.28
NetIC2_20: IC2.20 L3.1 | length 112
  Top Layer w8: IC2.20 1306.97,1403.94 1340.18,1437.15 1368.66,1465.63 L3.1
NetJP1_2: JP1.2 M1.10 R13.2 | length 441.7
  Top Layer w3.5: v1(2283.34,1048.54) 2369.82,962.07 2369.82,818.34 2363.92,812.44 JP1.2 2340,807.44 R13.2
  Bottom Layer w3.5: M1.10 2269.56,1034.76 v1(2283.34,1048.54)
NetJP2_2: JP2.2 M1.11 R14.2 | length 382.2
  Top Layer w3.5: v1(2283.34,1007.2) 2313.03,977.52 2313.03,818.99 ; JP2.2 2306.48,812.44 2313.03,818.99 ; R14.2 2305.69,770.16 2313.03,777.5 2313.03,818.99
  Bottom Layer w3.5: M1.11 v1(2283.34,1007.2)
NetM1_5: M1.5 R11.2 | length 704.7
  Top Layer w3.5: v1(2283.34,1186.34) 2357.56,1186.34 2538.71,1005.19 2538.71,827.05 2512.81,801.15 2494.28,801.15 2480,786.88 R11.2
  Bottom Layer w3.5: M1.5 2269.56,1172.56 v1(2283.34,1186.34)
NetM1_6: M1.6 R12.2 | length 657.8
  Top Layer w3.5: v1(2283.34,1145) 2375.28,1145 2509.31,1010.97 2509.31,827.13 2499.21,817.03 2481.29,817.03 2447.46,783.2 2447.46,772.62 R12.2
  Bottom Layer w3.5: M1.6 v1(2283.34,1145)
NetP9_B5: P9.B5 R31.1 | length 316.1
  Top Layer w3.5: v1(855.16,1281.85) 868.46,1268.54 P9.B5 ; v1(948.54,1118.28) 951.26,1115.56 951.26,1109.27 977.1,1083.43 R31.1
  Bottom Layer w3.5: v1(855.16,1281.85) 948.54,1188.47 v1(948.54,1118.28)
NetP10_A5: P10.A5 R30.1 | length 346.9
  Top Layer w3.5: P10.A5 916.27,947.07 918.48,947.07 917.6,946.19 v1(964.2,946.19) ; v1(1000,765.44) 1040.26,765.44 1082.28,723.41 R30.1
  Bottom Layer w3.5: v1(964.2,946.19) 1000,910.39 v1(1000,765.44)
NetP10_B5: P10.B5 R32.1 | length 287.8
  Top Layer w3.5: v1(845,847.44) 863.9,828.54 P10.B5 ; v1(957.36,722.44) R32.1
  Bottom Layer w3.5: v1(845,847.44) 900.26,792.18 904.83,792.18 957.36,739.64 v1(957.36,722.44)
NetR22_2: R22.2 U1.26 | length 182.8
  Top Layer w3.5: U1.26 1088.74,1048.46 1099.81,1059.54 1191.66,1059.54 1205.49,1073.36 1206.09,1073.36 1214.57,1081.84 R22.2
NetR33_1: R33.1 U1.9 | length 196.5
  Top Layer w3.5: U1.9 1069.05,781.19 1079.95,770.3 1169.48,770.3 1202.61,737.17 1202.61,727.55 R33.1
PA0/TOUCH_X1: IC1.66 P2.4 | length 625.3
  Top Layer w3.5: IC1.66 v1(1817.76,922.56)
  Bottom Layer w3.5: v1(1817.76,922.56) 1820.48,919.84 1820.48,895.48 2022.49,693.47 2188.97,693.47 P2.4
PA1/TOUCH_X2: IC1.65 P2.5 | length 597.9
  Top Layer w3.5: IC1.65 v1(1764.61,959.96)
  Bottom Layer w3.5: v1(1764.61,959.96) 1766.65,957.91 1766.65,926.79 2015.7,677.74 2104.7,677.74 P2.5
PA2/TOUCH_Y1: IC1.64 P4.1 | length 464.4
  Top Layer w3.5: v1(1748.86,885.16) IC1.64
  Bottom Layer w3.5: v1(1748.86,885.16) 1785.84,885.16 2027.84,643.16 2039.28,643.16 P4.1
PA3/TOUCH_Y2: IC1.63 P4.2 | length 481.3
  Top Layer w3.5: IC1.63 1733.11,712.48 1752.79,692.79 1889.65,692.79 P4.2
PC0/SPI0_CLK: IC1.59 P6.1 | length 348.7
  Top Layer w3.5: P6.1 1670.12,722.56 IC1.59
PC1/SPI0_CS: IC1.60 P4.5 | length 313.8
  Top Layer w3.5: P4.5 1665,631.16 1685.87,652.02 IC1.60
PC2/SPI0_MISO: IC1.61 P4.4 | length 331.4
  Top Layer w3.5: IC1.61 1701.61,680.83 P4.4
PC3/SPI0_MOSI: IC1.62 P4.3 | length 400.9
  Top Layer w3.5: IC1.62 1717.36,705.98 1746.28,677.06 1805.38,677.06 P4.3
PD0: IC1.6 P1.1 | length 1027
  Top Layer w3.5: IC1.6 v1(1701.61,1349.72)
  Bottom Layer w3.5: v1(1701.61,1349.72) 1701.61,1375.89 1772.16,1446.44 2394,1446.44 P1.1
PD1: IC1.7 P1.2 | length 1021.4
  Top Layer w3.5: v1(1685.87,1274.92) IC1.7
  Bottom Layer w3.5: v1(1685.87,1274.92) 1685.87,1382.41 1765.62,1462.17 2309.73,1462.17 P1.2
PD2: IC1.8 P1.3 | length 866.1
  Top Layer w3.5: IC1.8 v1(1670.12,1349.72)
  Bottom Layer w3.5: v1(1670.12,1349.72) 1670.12,1388.93 1759.08,1477.9 2225.46,1477.9 P1.3
PD3/UART1_RX: IC1.9 P1.4 | length 860.5
  Top Layer w3.5: v1(1654.37,1274.92) IC1.9
  Bottom Layer w3.5: v1(1654.37,1274.92) 1654.37,1395.46 1752.54,1493.63 2141.19,1493.63 P1.4
PD4/UART1_TX: IC1.10 P1.5 | length 705.3
  Top Layer w3.5: IC1.10 v1(1638.62,1349.72)
  Bottom Layer w3.5: v1(1638.62,1349.72) 1638.62,1401.98 1746,1509.36 2056.91,1509.36 P1.5
PD5: IC1.11 P3.1 | length 699.7
  Top Layer w3.5: v1(1622.87,1274.92) IC1.11
  Bottom Layer w3.5: v1(1622.87,1274.92) 1622.87,1408.5 1739.46,1525.09 1972.65,1525.09 P3.1
PD6: IC1.12 P3.2 | length 544.4
  Top Layer w3.5: IC1.12 v1(1607.13,1349.72)
  Bottom Layer w3.5: v1(1607.13,1349.72) 1607.13,1415.02 1732.92,1540.82 1888.38,1540.82 P3.2
PD7: IC1.13 P3.3 | length 538.8
  Top Layer w3.5: v1(1591.38,1274.92) IC1.13
  Bottom Layer w3.5: v1(1591.38,1274.92) 1591.38,1421.55 1726.97,1557.14 1804.7,1557.14 P3.3
PD8: IC1.14 P3.4 | length 383.6
  Top Layer w3.5: IC1.14 v1(1575.63,1349.72)
  Bottom Layer w3.5: v1(1575.63,1349.72) 1575.63,1428.07 P3.4
PD9: IC1.15 P3.5 | length 423.5
  Top Layer w3.5: v1(1559.88,1274.92) IC1.15
  Bottom Layer w3.5: v1(1559.88,1274.92) 1559.88,1434.59 1665,1539.71 P3.5
PD10: IC1.16 P5.1 | length 313.8
  Top Layer w3.5: IC1.16 v1(1544.13,1349.72)
  Bottom Layer w3.5: v1(1544.13,1349.72) 1544.13,1596.57 P5.1
PD11: IC1.17 P5.2 | length 406.2
  Top Layer w3.5: v1(1528.39,1274.92) IC1.17
  Bottom Layer w3.5: P5.2 1465,1529.89 1528.39,1466.51 v1(1528.39,1274.92)
PD12: IC1.18 P5.3 | length 366.3
  Top Layer w3.5: IC1.18 v1(1512.64,1349.72)
  Bottom Layer w3.5: P5.3 1365,1607.48 1512.64,1459.84 v1(1512.64,1349.72)
PD13/UART2_TX: IC1.19 P5.4 | length 515.6
  Top Layer w3.5: v1(1496.89,1274.92) IC1.19
  Bottom Layer w3.5: P5.4 1325.35,1557.1 1392.93,1557.1 1496.89,1453.14 v1(1496.89,1274.92)
PD14/UART2_RX: IC1.21 P5.5 | length 528.1
  Top Layer w3.5: IC1.21 1465.39,1372.65 v1(1467.08,1374.34)
  Bottom Layer w3.5: P5.5 1210,1572.44 1220,1572.44 1230,1562.44 1290,1562.44 1311.08,1541.37 1386.19,1541.37 1481.69,1445.87 1481.69,1388.95 v1(1467.08,1374.34)
PD15/I2C2_CLK: IC1.23 P7.1 | length 647.4
  Top Layer w3.5: v1(1420,1310) 1420,1282.91 IC1.23
  Bottom Layer w3.5: P7.1 1065,1557.44 1096.81,1525.64 1379.44,1525.64 1390.64,1514.43 1407.1,1497.97 1420.12,1484.95 1420.12,1310.12 v1(1420,1310)
PD16/I2C2_SDA: IC1.24 P7.2 | length 788
  Top Layer w3.5: IC1.24 v1(1457.52,1267.05)
  Bottom Layer w3.5: P7.2 1073.23,1509.21 1373.54,1509.21 1398.74,1484.01 1398.74,1291.26 1421.22,1268.78 1455.79,1268.78 v1(1457.52,1267.05)
PD17: IC1.25 P7.3 | length 809.5
  Top Layer w3.5: v1(1382.72,1251.3) IC1.25
  Bottom Layer w3.5: P7.3 990.47,1491.97 1317.47,1491.97 1382.72,1426.72 v1(1382.72,1251.3)
PD18: IC1.26 P7.4 | length 993.8
  Top Layer w3.5: IC1.26 v1(1457.52,1235.55)
  Bottom Layer w3.5: P7.4 825.16,1557.28 902.49,1557.28 983.75,1476.01 1311.43,1476.01 1362.14,1425.3 1362.14,1244.71 ; 1362.2,1244.65 1371.3,1235.55 v1(1457.52,1235.55)
PD19: IC1.27 P8.4 | length 1006.5
  Top Layer w3.5: v1(1382.72,1219.8) IC1.27
  Bottom Layer w3.5: P8.4 825.39,677.83 914.15,677.83 929.84,693.52 995,693.52 1021.48,719.99 1021.48,893.92 1347.36,1219.8 v1(1382.72,1219.8)
PD20: IC1.28 P8.3 | length 973.7
  Top Layer w3.5: IC1.28 v1(1457.52,1204.06)
  Bottom Layer w3.5: P8.3 876.28,617.44 936.22,677.38 1001.97,677.38 1037.36,712.76 1037.36,884.8 1356.5,1203.94 1380.99,1203.94 1381.1,1204.06 v1(1457.52,1204.06)
PD21: IC1.29 P8.2 | length 789.4
  Top Layer w3.5: v1(1382.72,1188.31) IC1.29
  Bottom Layer w3.5: P8.2 1053.59,706.03 1053.59,873.08 1364.96,1184.45 1375.02,1184.45 1376.15,1185.59 1380,1185.59 v1(1382.72,1188.31)
PE6/PWM1: IC1.43 P6.2 | length 390.9
  Top Layer w3.5: IC1.43 v1(1457.52,967.83)
  Bottom Layer w3.5: v1(1457.52,967.83) 1460.24,965.11 1460.24,622.2 P6.2
PE7/SPI1_CS: IC1.42 P6.3 | length 427.2
  Top Layer w3.5: v1(1382.72,983.58) IC1.42
  Bottom Layer w3.5: P6.3 1355.99,626.45 1355.99,972.04 1367.54,983.58 v1(1382.72,983.58)
PE8/SPI1_MOSI: IC1.41 P6.4 | length 555.7
  Top Layer w3.5: IC1.41 v1(1457.52,999.33)
  Bottom Layer w3.5: P6.4 1339.85,692.29 1339.85,978.32 1360.86,999.33 v1(1457.52,999.33)
PE9/SPI1_CLK: IC1.40 P6.5 | length 585.6
  Top Layer w3.5: v1(1382.72,1015.08) IC1.40
  Bottom Layer w3.5: P6.5 1165,634.87 1179.67,649.54 1179.67,651.22 1206.15,677.69 1279.51,677.69 1324.06,722.24 1324.06,986.14 1352.99,1015.08 v1(1382.72,1015.08)
PE10/SPI1_MISO: IC1.39 P8.1 | length 755.9
  Top Layer w3.5: IC1.39 v1(1457.52,1030.83)
  Bottom Layer w3.5: P8.1 1097.21,649.65 1141.99,694.43 1272.57,694.43 1307.64,729.5 1307.64,993.67 1344.79,1030.83 v1(1457.52,1030.83)
PE11/I2C0_CLK: IC1.38 JP1.1 | length 1235.6
  Top Layer w3.5: v1(1382.72,1046.57) IC1.38 ; v1@2344.72,886.82 2344.72,846.72 JP1.1
  Signal 2 w3.5: v1(1382.72,1046.57) 1402.8,1046.57 1414.11,1035.26 1414.11,899.55 1487.06,826.6 2284.25,826.6 v1(2344.72,887.07)
PE12/I2C0_SDA: IC1.37 JP2.1 | length 1147.7
  Top Layer w3.5: IC1.37 v1(1457.52,1062.32) ; JP2.1 v1(2285,887.07)
  Signal 2 w3.5: v1(1457.52,1062.32) 1457.19,1061.99 1440.27,1061.99 1429.33,1051.06 1429.33,919.98 1506.23,843.08 2241.01,843.08 v1(2285,887.07)
SDC0_CLK: IC1.56 TF1.5 | length 661.1
  Top Layer w3.5: v1(1622.87,885.16) IC1.56 ; TF1.5@2037.32,1089.67 2039.09,1091.44 v1(2088,1091.44)
  Bottom Layer w3.5: v1(1622.87,885.16) 1622.87,907.38 1717.06,1001.57 1843.33,1001.57 1855.01,1013.24 1887.8,1013.24 1895,1020.44 1969.56,1020.44 1980,1010 2006.56,1010 v1(2088,1091.44)
SDC0_CMD: IC1.55 R4.1 TF1.3 | length 1082.6
  Top Layer w3.5: IC1.55 v1(1607.13,959.96) ; v1(1989.2,1176.94) TF1.3@2037.32,1176.94 ; TF1.3 2113.84,1176.61 2200,1090.45 R4.1
  Bottom Layer w3.5: v1(1607.13,959.96) 1681.03,1033.87 1785,1033.87 1828.22,1077.09 1900.42,1077.09 1988.26,1164.93 1988.26,1175.99 v1(1989.2,1176.94)
SDC0_D0: IC1.57 R3.1 TF1.7 | length 815.4
  Top Layer w3.5: IC1.57 v1(1638.62,959.96) ; v1(1989.54,1036.36) 1992.53,1036.36 2025.51,1003.39 2119.09,1003.39 2165,957.47 R3.1
  Bottom Layer w3.5: v1(1638.62,959.96) 1696.1,1017.44 1836.65,1017.44 1845.02,1025.81 1870.39,1025.81 1880.94,1036.36 v1(1989.54,1036.36)
SDC0_D1: IC1.58 R2.1 TF1.8 | length 787.3
  Top Layer w3.5: v1(1654.37,885.16) IC1.58 ; v1(1989.2,960.4) TF1.8@2037.32,960.41 ; TF1.8 2122.35,960.08 2130,952.43 R2.1
  Signal 2 w3.5: v1(1654.37,885.16) 1681.72,857.81 1946.37,857.81 1989.2,900.64 v1(1989.2,960.4)
SDC0_D2: IC1.53 R6.1 TF1.1 | length 1279.9
  Top Layer w3.5: IC1.53 v1(1575.63,959.96) ; v1(1989.2,1263.55) TF1.1@2037.32,1263.56 ; TF1.1 2115.49,1263.23 2251.08,1127.64 2251.08,797.92 2263.38,785.62 2263.38,776.77 R6.1
  Bottom Layer w3.5: v1(1575.63,959.96) 1575.63,993.85 1648,1066.22 1759.23,1066.22 1955.21,1262.21 1987.86,1262.21 v1(1989.2,1263.55)
SDC0_D3: IC1.54 R5.1 TF1.2 | length 1269.8
  Top Layer w3.5: v1(1591.38,885.16) IC1.54 ; v1(1989.2,1219.91) TF1.2 2114.75,1219.92 2235,1099.67 R5.1
  Bottom Layer w3.5: v1(1591.38,885.16) 1591.38,975.69 1664.28,1048.59 1771,1048.59 1816.35,1093.94 1893.6,1093.94 1963.44,1163.79 1963.44,1189.33 1985.14,1211.02 1985.14,1212 1989.2,1216.07 v1(1989.2,1219.91)
UART0_RX: IC1.49 R22.1 | length 513.8
  Top Layer w3.5: R22.1 1256.49,1075.95 1256.49,1047.13 v1(1257.34,1046.28) ; IC1.49 v1(1512.64,959.96)
  Bottom Layer w3.5: v1(1257.34,1046.28) 1339.64,1128.58 1477.19,1128.58 1512.64,1093.13 v1(1512.64,959.96)
UART0_TX: IC1.48 U1.25 | length 722.8
  Top Layer w3.5: U1.25 1108.42,1036.11 1114.06,1041.74 1229.54,1041.74 1247.16,1024.12 v1(1272.91,1024.12) ; v1(1496.89,885.16) IC1.48
  Bottom Layer w3.5: v1(1272.91,1024.12) 1283.17,1034.38 1283.17,1051.6 1344.13,1112.56 1467.78,1112.56 1486.08,1094.26 1486.08,895.96 v1(1496.89,885.16)
USB_CP_N: P10.A7 P10.B7 U1.5 | length 275.1
  Top Layer w3.5: v1(842.98,881.02) 849.56,887.6 P10.A7 1009.84,887.6 U1.5 ; v1(866,926.97) P10.B7
  Signal 1 w3.5: v1(842.98,881.02) 866,904.04 v1(866,926.97)
USB_CP_P: P10.A6 P10.B6 U1.4 | length 275.1
  Top Layer w3.5: v1(842.98,913.86) 849.56,907.28 P10.A6 1009.84,907.28 U1.4 ; v1(866,867.91) P10.B6
  Signal 2 w3.5: v1(842.98,913.86) 866,890.84 v1(866,867.91)
USB_ID: IC1.44 P9.A5 R29.2 | length 782.8
  Top Layer w3.5: P9.A5 915.96,1386.55 963.89,1386.55 v1(964,1386.44) ; R29.2 1147.15,1086.44 v1(1175,1086.44) ; v1(1382.72,952.09) IC1.44
  Signal 2 w3.5: v1(1175,1086.44) 1177.2,1084.24 1185.76,1084.24 1317.91,952.09 v1(1382.72,952.09)
  Bottom Layer w3.5: v1(964,1386.44) 986,1386.44 1175,1197.44 v1(1175,1086.44)
USB_N: IC1.68 P9.A7 P9.B7 | length 1336.4
  Top Layer w3.5: v1(842.98,1321.02) 849.56,1327.6 P9.A7 958.1,1327.6 v1@966.26,1319.44 ; v1(866,1366.97) P9.B7 ; IC1.68 1846.29,967.83 1853.15,960.98 v1(1857,960.98)
  Signal 1 w3.5: v1(842.98,1321.02) 866,1344.04 v1(866,1366.97)
  Signal 2 w3.5: v1(967,1319.44) 969.72,1322.16 969.72,1327.61 972.8,1330.69 1067.66,1330.69 1277.91,1120.44 1654.91,1120.44 1803.1,972.25 1803.1,971.01 1805.15,968.96 1847.93,968.96 1855.91,960.98 v1(1857,960.98)
USB_P: IC1.69 P9.A6 P9.B6 | length 1336.4
  Top Layer w3.5: v1(842.98,1353.86) 849.56,1347.28 P9.A6 958.1,1347.28 966.26,1355.44 v1(967,1355.44) ; v1(866,1307.91) P9.B6 ; IC1.69 1846.29,983.58 1853.15,990.44 v1(1857,990.44)
  Signal 2 w3.5: v1(842.98,1353.86) 866,1330.84 v1(866,1307.91) ; v1(967,1355.44) 969.72,1352.72 969.72,1347.27 972.8,1344.19 1073.25,1344.19 1283.5,1133.94 1660.5,1133.94 1811.98,982.46 1847.93,982.46 1855.91,990.44 v1(1857,990.44)
VBUS: D1.1 P9.A4 P9.A9 P9.B4 P9.B9 P10.A4 P10.A9 P10.B4 P10.B9 R29.1 R33.2 TP1.1 U1.7 U1.8 | length 1140
  Top Layer w3.5: U1.8@1049.37,793.79 1049.37,778.57 1073.49,754.45 1141.25,754.45 1172.28,723.43 R33.2
  Top Layer w5: D1.1 1055,1151.73 1055,1087.84 TP1.1 1106.86,1081.58 R29.1
  Top Layer w10: v1(841,815.44) 843.09,815.44 849.67,808.86 P10.B4 ; v1(841,1255.44) 843.09,1255.44 849.67,1248.86 P9.B4 ; v1(860,966.34) 879.69,986.02 P10.B9 ; v1(860,1406.34) 879.69,1426.02 P9.B9 ; P10.A9 916.11,797.31 963.74,797.31 v1(964,797.58) ; P10.A4 v1(963,997.83) ; P9.A9 916.11,1237.31 963.74,1237.31 v1(964,1237.58) ; P9.A4 v1(963,1437.83) ; v1(985,1142.44) 1015.71,1142.44 D1.1 ; v1(985,1172.44) 1034.29,1172.44 D1.1 ; v1(985,1202.44) 1014.49,1202.44 1040,1176.93 D1.1 ; U1.7 996.22,848.39 965.48,817.64 965.48,799.05 v1(964,797.58) ; U1.8@1049.37,793.79 1045.59,797.58 v1(964,797.58)
VCC_1V2: C1.2 C23.2 C33.2 IC1.22 IC1.35 IC1.71 L3.2 R27.2 TP6.1 | length 1530.3
  Top Layer w3.5: v1(1278.38,1544.8) 1279.19,1544.8 1290,1533.99 R27.2 R27.2@1282.4,1525.47 ; IC1.35 v1(1457.52,1093.82) ; L3.2 TP6.1 ; IC1.71 1833,1015.08 1841.36,1023.44 1884,1023.44 1884.03,1024.4 1868.98,1039.45 1859.81,1039.45 v1(1857.09,1042.17)
  Top Layer w7: IC1.22 1449.65,1324.99 1449.58,1325.06 1448.75,1325.06 1443.02,1330.78 1443.02,1362.14 C23.2 1443.03,1372.76 1443.03,1397.13 C33.2 C33.2@1443.03,1407.76 ; L3.2 1443.03,1469.13 C33.2@1443.03,1407.76 ; v1(1465,1402.44) 1443.56,1402.44 1443.03,1402.97 C33.2@1443.03,1407.76
  Signal 1 w3.5: v1(1465,1402.44) 1438,1375.44 1438,1180.44 1457.52,1160.92 v1(1457.52,1093.82) 1805.44,1093.82 v1(1857.09,1042.17)
  Signal 2 w3.5: v1(1278.38,1544.8) 1427.64,1544.8 1465,1507.44 v1(1465,1402.44)
VCC_2V5: C26.2 C29.1 C31.2 C32.2 IC1.30 IC1.31 IC1.32 IC1.34 IC1.36 L2.2 R20.2 R25.1 TP5.1 | length 1250.3
  Top Layer w3.5: TP5.1@978.49,1527.44 988.49,1517.44 v1(1010,1517.44) ; v1(1175,1547.44) 1185,1537.44 R20.2 R20.2@1177.4,1525.47
  Top Layer w7: IC1.36 v1(1382.72,1078.07) 1382.72,1101.02 1391.26,1109.57 IC1.34 ; IC1.32 1399.85,1141.06 v1@1384.1,1156.81 ; IC1.31 v1@1384.1,1156.81 ; IC1.30 1399.85,1172.56 v1@1384.1,1156.81
  Top Layer w8: TP5.1 TP5.1@978.49,1527.44 ; v1(1010,1517.44) C26.2 1040,1462.83 L2.2
  Top Layer w10: v1(1281,1208.44) 1282.86,1210.3 1291.13,1210.3 C31.2@1305,1224.17 ; C31.2 C31.2@1305,1224.17 ; v1@1384.1,1156.81 v1(1382.72,1156.81) 1343.94,1156.81 C29.1 R25.1 C32.2 C31.2@1305,1224.17
  Signal 1 w8: v1(1382.72,1078.07) v1(1382.72,1156.81)
  Signal 1 w10: v1(1175,1547.44) 1175,1355 1281,1249 v1(1281,1208.44)
  Signal 2 w3.5: v1(1010,1517.44) 1040,1547.44 v1(1175,1547.44)
VCC_3V3: C9.1 C10.2 C12.2 C13.2 C20.2 C21.2 IC1.4 IC1.5 IC1.20 IC1.50 IC1.67 L1.2 M1.4 P7.5 R1.2 R2.2 R3.2 R4.2 R5.2 R6.2 R9.2 R10.1 R11.1 R13.1 R14.1 R17.2 R19.2 R21.1 R24.1 TF1.4 TP4.1 | length 4990.9
  Top Layer w3.5: R17.2 1250.6,1227.01 1258.64,1218.97 1258.64,1188.8 v1(1273,1174.44) ; v1(1261,972.44) 1261,984.44 1291.65,1015.09 1324.31,1015.09 1332.35,1007.06 1332.35,995.09 R21.1 ; R19.2 R24.1 1342.84,870.28 v1(1375.18,870.28) ; IC1.20 v1(1481.14,1349.72) ; R9.2 1929.28,1056 v1(1960,1056) ; R9.2@1927,1052.44 1927,1050.56 R9.2@1933.75,1043.8
  Top Layer w5: R1.2 1932.18,989.19 1959.19,989.19 v1(1960.07,990.07)
  Top Layer w7: C20.2 1502.71,837.44 1502.71,850.15 v1(1522,869.44) ; v1@1522.73,866.32 1522.73,873.07 1528.39,878.73 IC1.50 ; v1(1612,1519.44) 1678,1519.44 1713.42,1484.02 1714.12,1484.02 1725,1473.14 1725,1397.44 C13.2 1727,1385.44 1727,1343.85 ; IC1.5 1717.36,1334.21 1727,1343.85 ; IC1.4 1733.11,1337.74 1727,1343.85 ; IC1.67 1829.83,952.09 1842.24,939.68 1882.24,939.68 C9.1 C10.2 1889.5,911.94 1889.5,880.94 v1(1889,880.44)
  Top Layer w8: L1.2 L1.2@1176.06,1167.16 ; C21.2 1246.42,1172.58 1271.14,1172.58 v1(1273,1174.44)
  Top Layer w10: L1.2@1176.06,1167.16 C21.2 ; R2.2 R3.2 R4.2 R5.2 R6.2 R14.1 R13.1 R10.1 2374.22,733.94 v1(2374.22,707.22) ; v1(2480,707.22) R11.1
  Top Layer w15: v1(1989.2,1133.3) TF1.4
  Signal 1 w7: v1(1481.14,1349.72) 1483,1351.58 1483,1357.2 1612,1486.2 v1(1612,1519.44)
  Signal 1 w10: v1(1889,880.44) 2009.44,760 v1(2035,760)
  Signal 1 w15: P7.5 727.44,1555 912.44,1555 1140,1327.44 1140,1307.44 v1(1273,1174.44) 1300,1147.44 1300,1010.44 v1@1262,972.44 ; v1(1375.18,870.28) 1448.16,870.28 1463.44,855 1507.46,855 1521.9,869.44 v1(1522,869.44) ; v1(1960,1056) 1960,1104.1 v1(1989.2,1133.3)
  Signal 2 w8: v1@1960,990.14 v1(1960.07,990.07)
  Signal 2 w10: v1(2035,760) 2321.44,760 ; v1(2374.22,707.22) 2321.44,760 ; v1(2480,707.22) 2427.22,760 2321.44,760
  Signal 2 w15: v1(1261,972.44) 1362.64,870.8 1374.66,870.8 v1(1375.18,870.28) ; v1(1273,1174.44) 1293,1174.44 1340,1221.44 1340,1284.44 1398.58,1343.02 1473.7,1343.02 1480.41,1349.72 v1(1481.14,1349.72) ; v1(1522,869.44) 1575,922.44 1767,922.44 1809,880.44 v1(1889,880.44) ; v1@1960,990.14 v1(1960,1056)
  Bottom Layer w15: v1(1889,880.44) 1960.07,951.51 v1(1960.07,990.07) ; v1(1989.2,1133.3) 2008.3,1133.3 2074.28,1199.28 2184.16,1199.28 M1.4
VCC_5V: C14.2 C15.2 C16.1 C24.2 D1.2 IC2.7 IC2.8 IC2.9 IC2.10 IC2.16 IC2.18 IC2.19 IC3.3 M1.2 P2.2 TP2.1 | length 3829.1
  Top Layer w7: v1(1295,1312.44) TP2.1
  Top Layer w8: v1(1015,1267.44) 1015,1328.15 D1.2 1065,1328.15 v1(1065,1267.44) ; C24.2 1130.84,1358.28 1131.83,1358.28 1131.83,1359.27 1160.75,1388.19 IC2.7 ; C24.2@1127.6,1349.84 1142.6,1349.84 1151.5,1340.94 IC2.10 ; IC2.9 1134.35,1356.69 1150.1,1372.44 IC2.8 ; IC2.16 1294.94,1340.94 1295,1340.88 v1(1295,1312.44) ; IC2.18 1315,1372.44 v1@1333.14,1390.58 ; IC2.19 1328.12,1388.19 1332.37,1392.44 v1(1335,1392.44) 1337.63,1392.44 1342.17,1396.98 1359.54,1396.98 C14.2
  Top Layer w15: v1(1040,1267.44) D1.2 ; v1(1755,772.44) 1755.52,772.96 1761.47,772.96 1780.89,792.38 1789.94,792.38 C15.2 C16.1 1851,757.44 1880,728.44 IC3.3 1907,725.44 v1(1930,702.44)
  Top Layer w20: D1.2 1040,1352.44 C24.2
  Signal 1 w15: v1(1250,855) 1332.56,772.44 v1(1755,772.44) ; v1(2310,1255) 2403,1162 v1(2403,681)
  Signal 2 w8: v1(1143.53,1370.32) 1145.39,1372.18 1152.26,1372.18 1152.83,1372.75 1274.69,1372.75 ; v1(1295,1312.44) 1295,1352.44 1274.69,1372.75 ; v1(1335,1392.44) 1315.31,1372.75 1274.69,1372.75
  Signal 2 w15: v1(1040,1267.44) 1040,1065 v1(1250,855) ; v1(1930,702.44) 2325,702.44 2346.44,681 v1(2403,681) 2403.52,680.48 v1@2403.52,678.92
  Bottom Layer w15: v1(1755,772.44) 1837.56,772.44 1907.56,702.44 v1(1930,702.44) ; M1.2 2185.12,1255.12 2309.88,1255.12 v1(2310,1255) ; v1@2403.52,678.92 P2.2
pads on no net: IC1.1 IC1.72 IC1.75 IC1.76 IC1.77 IC1.78 IC1.84 IC1.85 IC1.86 IC1.87 IC1.88 M1.1 M1.13 P9.0 P9.A8 P9.B8 P10.0 P10.A8 P10.B8 TF1.14 TF1.15 U1.1 U1.2 U1.6 U1.10 U1.11 U1.12 U1.13 U1.14 U1.15 U1.16 U1.17 U1.18 U1.19 U1.20 U1.21 U1.22 U1.23 U1.24 U1.27 U1.28

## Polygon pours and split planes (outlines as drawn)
VBUS on Signal 2 "NONET_L01_P-001" (solid, pour order 1): 895,1300 864,1269 835,1269 828,1262 828,1249 835,1242 850.44,1242 895,1197.44 895,1022.44 845,972.44 845,957.44 855,947.44 880,947.44 895,932.44 895,842.44 880,827.44 830,827.44 830,782.44 1000,782.44 1000,1242.44 935,1307.44 935,1372.44 980,1417.44 980,1457.44 845,1457.44 845,1402.44 855,1392.44 875,1392.44 895,1372.44
GND on Signal 2 "NONET_L01_P-001" (solid, pour order 4): 2615,570 615,570 615,1664.88 2615,1664.88
GND on Bottom Layer "NONET_L01_P-001" (hatched 45Degree grid 20 track 8, pour order 5): 2615,570 615,570 615,1664.88 2615,1664.88
GND on Signal 1 "NONET_L01_P-001" (solid, pour order 3): 2615,570 615,570 615,1664.88 2615,1664.88
GND on Top Layer "NONET_L01_P-001" (hatched 45Degree grid 20 track 8, pour order 2): 2615,570 615,570 615,1664.88 2615,1664.88

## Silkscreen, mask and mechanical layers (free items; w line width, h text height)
Top Overlay:
  drawing of 21 lines, arcs and shapes, not listed
  text "HOST-DEVICE" at 871,1555 h20 r180
  text "RST" at 1805,1516 h20 r270
  text "FLIP - LINUX DEV BOARD" at 2046.84,1512.5 h25
  text "3V3" at 1680,1506 h20 r270
  text "2V5" at 955,1501 h20 r270
  text "1V2" at 1500,1446 h20 r270
  text "5V0" at 1380,1346 h20 r270
  text "USB" at 816,1150 h20 r180
  text "SERIAL" at 734,1090 h20
  text "VBUS" at 1022.69,1035 h20
  text "USR" at 1231.68,937 h20
  text "SYS" at 1231.68,897 h20
  text "A3V0" at 2010,846 h20 r270
  text "USR" at 1232.68,815 h20
  text "BY POWER LIN" at 2122.07,685 h20
  text "CP2102" at 724,680 h20
Bottom Overlay:
  drawing of 36 lines, arcs and shapes, not listed
  text "PD1" at 2445.01,1460.32 h40 r270
  text "PD9" at 1645.01,1446.99 h40 r270
  text "PD8" at 1745.01,1446.99 h40 r270
  text "PD7" at 1845.01,1446.99 h40 r270
  text "PD6" at 1945.01,1446.99 h40 r270
  text "PD5" at 2045.01,1446.99 h40 r270
  text "PD4" at 2145.01,1446.99 h40 r270
  text "PD3" at 2245.01,1446.99 h40 r270
  text "PD2" at 2345.01,1446.99 h40 r270
  text "PD0" at 2545.01,1446.99 h40 r270
  text "PD11" at 1445.01,1426.99 h40 r270
  text "PD16" at 945.01,1413.66 h40 r270
  text "PD15" at 1045.01,1413.66 h40 r270
  text "PD14" at 1145.01,1413.66 h40 r270
  text "PD13" at 1245.01,1413.66 h40 r270
  text "PD12" at 1345.01,1413.66 h40 r270
  text "PD10" at 1545.01,1413.66 h40 r270
  text "3V3" at 645.01,1366.99 h40 r270
  text "PD18" at 745.01,1333.66 h40 r270
  text "PD17" at 845.01,1333.66 h40 r270
  text "FLIP" at 755.01,1012.53 h60 r270
  text "V0.1 Beta" at 635.37,987.9 h60 r270
  text "GND" at 645.01,757 h40 r270
  text "PD19" at 745.01,757 h40 r270
  text "PD20" at 845.01,757 h40 r270
  text "PD21" at 945.01,687 h40 r270
  text "PE10" at 1045.01,687 h40 r270
  text "PE9" at 1145.01,687 h40 r270
  text "PE8" at 1245.01,687 h40 r270
  text "PE7" at 1345.01,687 h40 r270
  text "PE6" at 1445.01,687 h40 r270
  text "PC0" at 1545.01,687 h40 r270
  text "PC1" at 1645.01,687 h40 r270
  text "PC2" at 1745.01,687 h40 r270
  text "PC3" at 1845.01,687 h40 r270
  text "PA3" at 1945.01,687 h40 r270
  text "PA2" at 2045.01,687 h40 r270
  text "PA1" at 2145.01,687 h40 r270
  text "PA0" at 2245.01,687 h40 r270
  text "ADC0" at 2345.01,687 h40 r270
  text "5V" at 2445.01,687 h40 r270
  text "GND" at 2545.01,687 h40 r270
Mechanical 1:
  the board outline again, w5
